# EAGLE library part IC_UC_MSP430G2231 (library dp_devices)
Ultra Low Power Mixed signal microcontroller
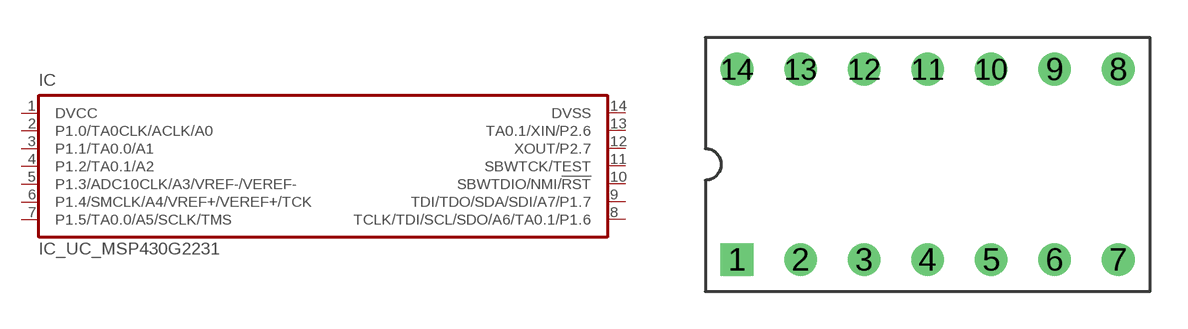
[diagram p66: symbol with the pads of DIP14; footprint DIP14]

Designator prefix IC

## IC_UC_MSP430G2231  [DIP14]
1  DVCC  pwr
2  P1.0/TA0CLK/ACLK/A0
3  P1.1/TA0.0/A1
4  P1.2/TA0.1/A2
5  P1.3/ADC10CLK/A3/VREF-/VEREF-
6  P1.4/SMCLK/A4/VREF+/VEREF+/TCK
7  P1.5/TA0.0/A5/SCLK/TMS
8  TCLK/TDI/SCL/SDO/A6/TA0.1/P1.6
9  TDI/TDO/SDA/SDI/A7/P1.7
10  SBWTDIO/NMI/!RST  in
11  SBWTCK/TEST  in
12  XOUT/P2.7
13  TA0.1/XIN/P2.6
14  DVSS  pwr

## Footprint DIP14 (pad centres in mm)
drill 0.8 square: 1 -7.62,-3.81
drill 0.8 round: 2 -5.08,-3.81; 3 -2.54,-3.81; 4 0,-3.81; 5 2.54,-3.81; 6 5.08,-3.81; 7 7.62,-3.81; 8 7.62,3.81; 9 5.08,3.81; 10 2.54,3.81; 11 0,3.81; 12 -2.54,3.81; 13 -5.08,3.81; 14 -7.62,3.81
